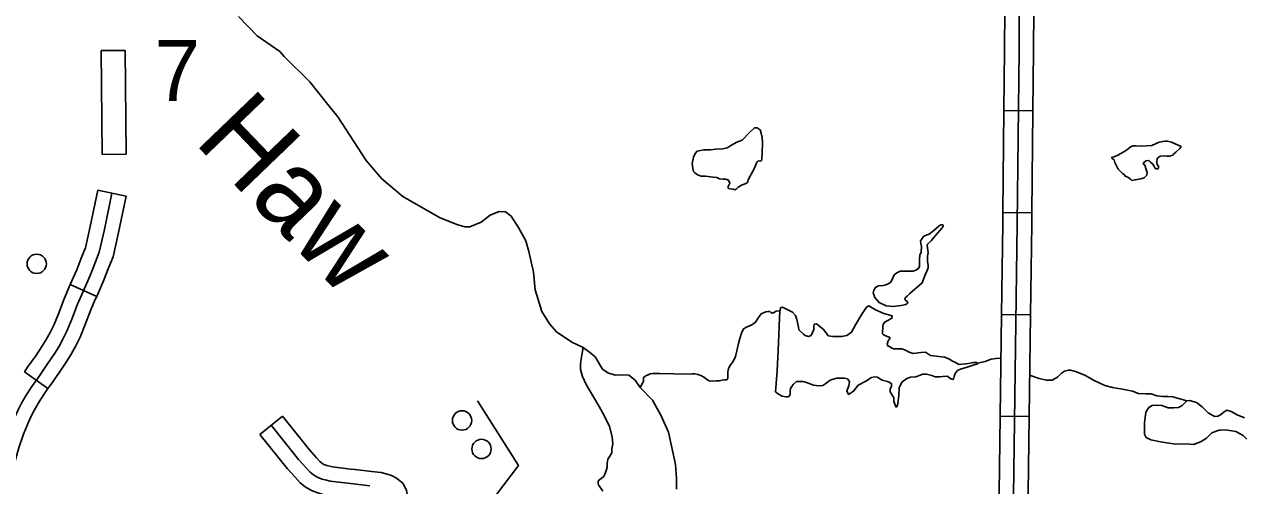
# Model space of a CAD drawing. Extents: x 1382482 to 1385815, y 1168351 to 1170484.
# Drawn here: x 1383658.5 to 1383911.3, y 1169178.5 to 1169274 of the extents above; entities that cross this region are included whole.
import ezdxf

# ---------------------------------------------------------------- set-up
doc = ezdxf.new("R2010")
doc.units = 0
for name, color, linetype in [('32', 7, 'Continuous'), ('35', 7, 'Continuous'), ('45', 7, 'Continuous'), ('57', 7, 'Continuous'), ('Default', 7, 'Continuous')]:
    doc.layers.add(name, color=color, linetype=linetype)

msp = doc.modelspace()

# ---------------------------------------------------------------- linework, layer by layer
at = {"layer": '32'}
for p, q in [((1383867.57, 1169256.11), (1383861.57, 1169256.18)), ((1383673.68, 1169239.69), (1383679.56, 1169238.46)), ((1383867.34, 1169234.99), (1383861.34, 1169235.06)), ((1383667.99, 1169220.11), (1383673.46, 1169217.66)), ((1383867.07, 1169213.87), (1383861.07, 1169213.95)), ((1383658.47, 1169202.04), (1383663.35, 1169198.55)), ((1383866.79, 1169192.75), (1383860.79, 1169192.83))]:
    msp.add_line(p, q, dxfattribs=at)
for points in [[(1383862.28, 1169023.84), (1383862.44, 1169032.46), (1383862.63, 1169053.65), (1383862.71, 1169067.33), (1383862.71, 1169079.26), (1383862.86, 1169103.72), (1383863.17, 1169145.65), (1383864.32, 1169232.68), (1383864.7, 1169268.66), (1383864.78, 1169287.98), (1383865.16, 1169308.27), (1383865.27, 1169315.78)], [(1383861.57, 1169256.18), (1383861.7, 1169268.68), (1383861.74, 1169277.27)], [(1383867.57, 1169256.11), (1383867.7, 1169268.64), (1383867.74, 1169277.25)], [(1383861.34, 1169235.06), (1383861.57, 1169256.18)], [(1383867.34, 1169234.99), (1383867.57, 1169256.11)], [(1383676.62, 1169239.07), (1383675.05, 1169231.55), (1383674, 1169226.81), (1383673.19, 1169224.84), (1383672.13, 1169222.01), (1383670.36, 1169218.07), (1383669.49, 1169216.04), (1383668.3, 1169212.93), (1383667.29, 1169210.46), (1383666.46, 1169208.79), (1383665.58, 1169207.2), (1383664.75, 1169205.89), (1383663.29, 1169203.66), (1383661.58, 1169201.23), (1383659.99, 1169199.01), (1383658.85, 1169197.17), (1383657.87, 1169195.53), (1383657.16, 1169194.19), (1383656.53, 1169192.75), (1383655.47, 1169190.21), (1383654.44, 1169187.16), (1383653.68, 1169184.48), (1383653, 1169182.54), (1383652.14, 1169180.57)], [(1383673.68, 1169239.69), (1383672.12, 1169232.18), (1383671.12, 1169227.71), (1383670.39, 1169225.93), (1383669.35, 1169223.15), (1383667.99, 1169220.11)], [(1383679.56, 1169238.46), (1383677.99, 1169230.92), (1383676.87, 1169225.9), (1383675.98, 1169223.74), (1383674.9, 1169220.87), (1383673.46, 1169217.66)], [(1383861.07, 1169213.95), (1383861.32, 1169232.72), (1383861.34, 1169235.06)], [(1383867.07, 1169213.87), (1383867.32, 1169232.65), (1383867.34, 1169234.99)], [(1383667.99, 1169220.11), (1383667.61, 1169219.28), (1383666.71, 1169217.16), (1383665.51, 1169214.03), (1383664.56, 1169211.7), (1383663.81, 1169210.19), (1383663, 1169208.74), (1383662.22, 1169207.51), (1383660.81, 1169205.34), (1383659.13, 1169202.97), (1383658.47, 1169202.04)], [(1383673.46, 1169217.66), (1383673.11, 1169216.87), (1383672.27, 1169214.91), (1383671.09, 1169211.83), (1383670.03, 1169209.22), (1383669.12, 1169207.39), (1383668.16, 1169205.67), (1383667.27, 1169204.27), (1383665.78, 1169201.97), (1383664.02, 1169199.49), (1383663.35, 1169198.55)], [(1383860.79, 1169192.83), (1383861.07, 1169213.95)], [(1383866.79, 1169192.75), (1383867.07, 1169213.87)], [(1383663.35, 1169198.55), (1383662.49, 1169197.35), (1383661.42, 1169195.61), (1383660.48, 1169194.05), (1383659.86, 1169192.88), (1383659.29, 1169191.57), (1383658.28, 1169189.15), (1383657.3, 1169186.27), (1383656.54, 1169183.58), (1383655.15, 1169179.6)], [(1383860.51, 1169171.71), (1383860.79, 1169192.83)], [(1383866.51, 1169171.63), (1383866.79, 1169192.75)]]:
    msp.add_lwpolyline(points, dxfattribs=at)
at = {"layer": '35'}
for points in [[(1383702.85, 1169275.68), (1383706.7, 1169271.69), (1383711.41, 1169268.41), (1383712.36, 1169267.36), (1383717.64, 1169262.11), (1383721.37, 1169257.46), (1383723.47, 1169254.88), (1383729.33, 1169245.82), (1383732.61, 1169242.01), (1383736.95, 1169238.36), (1383744.57, 1169234), (1383748.15, 1169232.6), (1383749.78, 1169232.07), (1383750.8, 1169232.07), (1383753.2, 1169233.07), (1383755.04, 1169234.51), (1383756.92, 1169235.28), (1383758.21, 1169235.2), (1383759.41, 1169234.28), (1383761.02, 1169231.82), (1383762.42, 1169229.18), (1383763.04, 1169227), (1383764.01, 1169222.68), (1383764.36, 1169219.03), (1383765.76, 1169214.51), (1383767.32, 1169211.99), (1383768.79, 1169210.35), (1383772, 1169208.19), (1383774.33, 1169207.1), (1383775.66, 1169206.09), (1383776.78, 1169205.16), (1383778.34, 1169202.59), (1383779.47, 1169201.82), (1383780.98, 1169201.31), (1383782.5, 1169201.43), (1383783.78, 1169201.31), (1383785.1, 1169200.28), (1383786.17, 1169198.8), (1383788.68, 1169196.14), (1383790.43, 1169193.02), (1383792.05, 1169189.52), (1383793.48, 1169182.82)], [(1383800.72, 1169248.05), (1383801.84, 1169248.21), (1383803.25, 1169248.26), (1383804.17, 1169248.44), (1383805.11, 1169249.04), (1383806.2, 1169249.62), (1383807.3, 1169250.06), (1383808.8, 1169251.64), (1383809.86, 1169252.59), (1383810.41, 1169252.61), (1383811.01, 1169252.17), (1383811.24, 1169251.48), (1383811.45, 1169250.61), (1383811.52, 1169249.55), (1383811.47, 1169247.38), (1383811.4, 1169246.16), (1383811.28, 1169245.82), (1383810.94, 1169245.7), (1383810.64, 1169245.79), (1383810.32, 1169245.52), (1383810.04, 1169244.83), (1383809.81, 1169244.14)], [(1383884.59, 1169245.39), (1383884.43, 1169245.96), (1383884.25, 1169246.14), (1383883.96, 1169246.33), (1383883.93, 1169246.51), (1383884.43, 1169246.58), (1383885.3, 1169246.98), (1383886.63, 1169247.77), (1383887.28, 1169248.2), (1383887.83, 1169248.64), (1383888.37, 1169248.85), (1383888.95, 1169248.85), (1383890.06, 1169248.78), (1383892.2, 1169248.96), (1383893.75, 1169249.65), (1383894.9, 1169249.83), (1383895.48, 1169249.83), (1383896.28, 1169249.61), (1383898.32, 1169248.75)], [(1383809.81, 1169244.14), (1383809.19, 1169243.01), (1383808.98, 1169242.59), (1383808.57, 1169241.81), (1383808.48, 1169241.49), (1383808.38, 1169241.3), (1383808.2, 1169241.17), (1383807.92, 1169241), (1383807.3, 1169240.82), (1383806.82, 1169240.52), (1383806.36, 1169240.22), (1383806.04, 1169239.88), (1383805.76, 1169239.78), (1383805.46, 1169239.9), (1383804.88, 1169239.94), (1383804.45, 1169240.06), (1383804.35, 1169240.29), (1383804.38, 1169240.45), (1383804.63, 1169240.84), (1383804.77, 1169241.17), (1383804.49, 1169241.74), (1383803.94, 1169241.97), (1383803.25, 1169241.99), (1383802.56, 1169242.02), (1383802.01, 1169242.29), (1383801.25, 1169242.41), (1383799.66, 1169242.57), (1383798.81, 1169242.59), (1383798.02, 1169242.87), (1383797.49, 1169243.28), (1383797.22, 1169243.58), (1383797.03, 1169244.27), (1383796.96, 1169245.2), (1383797.19, 1169246.51), (1383797.54, 1169247.27), (1383797.93, 1169247.75), (1383799.33, 1169248.03), (1383800.72, 1169248.05)], [(1383898.32, 1169248.75), (1383898.01, 1169248.35), (1383897.21, 1169247.59), (1383896.78, 1169247.19), (1383896.56, 1169246.94), (1383896.13, 1169246.8), (1383895.81, 1169246.72), (1383895.34, 1169246.76), (1383894.72, 1169246.8), (1383893.98, 1169246.74), (1383893.33, 1169246.27), (1383893.28, 1169245.57), (1383893.28, 1169245.35), (1383893.35, 1169245.03), (1383893.6, 1169244.66), (1383893.6, 1169244.34), (1383893.53, 1169244.19), (1383893.42, 1169244.09), (1383893.35, 1169244.09), (1383893.13, 1169244.12), (1383892.88, 1169244.3), (1383892.63, 1169244.74), (1383892.41, 1169245.1), (1383891.94, 1169245.49), (1383891.62, 1169245.86), (1383891.08, 1169245.79), (1383890.68, 1169245.54), (1383890.46, 1169245.13), (1383890.79, 1169244.84), (1383891.08, 1169243.94), (1383891.29, 1169243.33), (1383891.18, 1169242.79), (1383890.61, 1169242.21), (1383889.96, 1169242.03), (1383888.8, 1169241.81), (1383888.12, 1169241.7), (1383887.79, 1169241.95), (1383887.25, 1169242.35), (1383886.67, 1169242.57), (1383886.56, 1169242.89), (1383886.13, 1169243.15), (1383885.23, 1169244.01), (1383884.59, 1169245.39)], [(1383844.05, 1169223.9), (1383844.08, 1169225.3), (1383844.1, 1169226.22), (1383844.42, 1169226.81), (1383844.49, 1169227.98), (1383844.36, 1169228.62), (1383844.29, 1169229.19), (1383844.47, 1169229.49), (1383844.83, 1169229.99), (1383845.09, 1169230.22), (1383846.05, 1169230.56), (1383847.05, 1169231.36), (1383848.17, 1169232.3), (1383848.53, 1169232.52), (1383848.74, 1169232.5), (1383849.01, 1169232.34), (1383848.83, 1169231.93), (1383847.28, 1169230.19), (1383846.5, 1169229.19), (1383845.73, 1169228.5), (1383845.63, 1169228.23), (1383845.82, 1169227.25), (1383845.89, 1169226.68), (1383845.75, 1169226.04), (1383845.73, 1169224.87), (1383845.89, 1169224.16), (1383845.84, 1169223.57), (1383845.57, 1169222.93), (1383845.26, 1169222.12)], [(1383845.26, 1169222.12), (1383844.6, 1169220.47), (1383843.09, 1169219.19), (1383842.04, 1169218.28), (1383841.49, 1169217.75), (1383841.1, 1169217.39), (1383841.03, 1169217.11), (1383841.26, 1169216.84), (1383841.51, 1169216.64), (1383841.65, 1169216.45), (1383841.6, 1169216.27), (1383841.22, 1169216), (1383840.23, 1169215.79), (1383838.68, 1169215.58), (1383837.13, 1169215.72), (1383835.69, 1169216.43), (1383834.82, 1169217.41), (1383834.61, 1169218.05), (1383834.48, 1169218.44), (1383834.57, 1169218.99), (1383834.91, 1169219.54), (1383835.57, 1169219.83), (1383836.53, 1169219.9), (1383837.06, 1169220.08), (1383837.45, 1169220.2), (1383838.02, 1169220.56), (1383838.38, 1169221.14), (1383838.63, 1169221.66), (1383838.84, 1169222.12), (1383839.39, 1169222.55), (1383840.05, 1169222.87), (1383841.03, 1169222.89), (1383841.51, 1169222.89), (1383842.2, 1169222.92), (1383842.77, 1169222.92), (1383843.32, 1169223.08), (1383843.86, 1169223.47), (1383844.05, 1169223.9)], [(1383815.12, 1169214.66), (1383814.34, 1169214.6), (1383813.86, 1169214.33), (1383813.63, 1169214.19), (1383813.63, 1169214.19), (1383813.22, 1169214.35), (1383813.01, 1169214.51), (1383812.71, 1169214.56), (1383812.19, 1169214.46), (1383811.25, 1169214.03), (1383810.66, 1169213.28), (1383810.09, 1169212.36), (1383809.33, 1169211.81), (1383808.35, 1169211.36), (1383807.58, 1169210.92), (1383807.16, 1169210.06), (1383806.84, 1169208.91), (1383806.52, 1169207.89), (1383806.18, 1169206.38), (1383805.89, 1169205.24), (1383805.42, 1169204.17), (1383804.87, 1169203.49), (1383804.62, 1169203.01), (1383804.41, 1169202.44), (1383804.32, 1169201.87), (1383804.32, 1169201.36), (1383804.32, 1169200.75), (1383804.18, 1169200.47), (1383803.96, 1169200.36), (1383803.66, 1169200.38), (1383803.13, 1169200.34), (1383802.61, 1169200.18), (1383801.9, 1169200.15), (1383801.12, 1169200.13), (1383800.42, 1169200.18), (1383799.98, 1169200.47), (1383799.5, 1169200.86), (1383798.73, 1169201.29), (1383798.09, 1169201.5), (1383797.45, 1169201.61), (1383796.92, 1169201.61), (1383796.35, 1169201.57), (1383793.14, 1169201.64), (1383790.17, 1169201.71), (1383788.67, 1169201.68), (1383788.19, 1169201.61), (1383787.78, 1169201.43), (1383787.32, 1169201.2), (1383787.09, 1169201.04), (1383786.86, 1169200.88), (1383786.84, 1169200.5), (1383786.82, 1169200.04), (1383786.66, 1169199.7), (1383786.17, 1169198.8)], [(1383842.22, 1169200.93), (1383841.45, 1169200.66), (1383840.4, 1169199.88), (1383839.86, 1169198.74), (1383839.76, 1169197.18), (1383839.54, 1169195.4), (1383839.35, 1169194.81), (1383839.17, 1169194.76), (1383838.99, 1169195.17), (1383838.76, 1169195.86), (1383838.71, 1169196.63), (1383838.3, 1169197.32), (1383837.98, 1169197.87), (1383837.98, 1169198.46), (1383838.26, 1169199.06), (1383838.26, 1169199.56), (1383837.94, 1169199.83), (1383837.44, 1169200.06), (1383836.34, 1169200.29), (1383835.65, 1169200.75), (1383835.33, 1169200.93), (1383834.74, 1169201.02), (1383834.1, 1169200.84), (1383832.91, 1169200.11), (1383831.36, 1169199.24), (1383830.4, 1169198), (1383829.35, 1169197.37), (1383828.99, 1169198.1), (1383829.44, 1169199.1), (1383829.58, 1169200.02), (1383829.12, 1169200.56), (1383828.53, 1169200.7), (1383827.84, 1169200.75), (1383826.93, 1169200.7), (1383825.65, 1169200.38), (1383825.06, 1169199.97), (1383824.65, 1169199.6), (1383824.05, 1169199.19), (1383823.41, 1169199.1), (1383822.64, 1169199.19), (1383822.09, 1169199.24), (1383820.63, 1169199.83), (1383819.85, 1169200.02), (1383819.53, 1169200.06), (1383818.57, 1169200.02), (1383817.89, 1169199.38), (1383817.34, 1169198.6), (1383817.25, 1169198.1), (1383817.25, 1169197.27), (1383816.88, 1169196.86), (1383816.38, 1169196.82), (1383815.56, 1169197), (1383814.83, 1169197.41), (1383814.23, 1169197.91), (1383814.55, 1169202.21), (1383814.83, 1169208.01), (1383814.96, 1169211.57), (1383815.12, 1169214.66), (1383815.33, 1169215.37), (1383815.69, 1169215.46), (1383816.24, 1169215.18), (1383817.75, 1169214.41), (1383818.37, 1169213.72), (1383818.6, 1169212.9), (1383818.94, 1169211.3), (1383819.07, 1169210.71), (1383820.03, 1169209.84), (1383820.35, 1169209.56), (1383821.04, 1169209.34), (1383821.59, 1169209.56), (1383821.91, 1169210.16), (1383822.13, 1169210.8), (1383822.13, 1169211.39), (1383822.23, 1169211.89), (1383822.64, 1169211.99), (1383822.91, 1169211.85), (1383823.46, 1169211.39), (1383824.19, 1169210.84), (1383824.83, 1169209.93), (1383825.14, 1169209.52)], [(1383825.14, 1169209.52), (1383826.14, 1169209.33), (1383827.14, 1169209.33), (1383827.97, 1169209.38), (1383829.02, 1169209.56), (1383829.98, 1169210.25), (1383830.8, 1169211.8), (1383832.12, 1169213.99), (1383833.1, 1169215.46), (1383833.55, 1169215.73), (1383834.91, 1169214.86), (1383836.65, 1169214.13), (1383838.38, 1169213.67), (1383838.34, 1169213.13), (1383838.02, 1169212.99), (1383837.65, 1169212.71), (1383836.92, 1169212.39), (1383836.51, 1169211.94), (1383836.46, 1169211.48), (1383836.46, 1169211.07), (1383836.42, 1169210.48), (1383836.37, 1169209.93), (1383836.74, 1169209.61), (1383837.19, 1169209.42), (1383837.7, 1169209.24), (1383837.88, 1169209.2), (1383837.88, 1169208.97), (1383837.56, 1169208.46), (1383837.33, 1169207.78), (1383837.47, 1169207.41), (1383838.67, 1169206.82), (1383839.52, 1169206.82), (1383840.39, 1169206.82), (1383841.17, 1169206.55), (1383841.9, 1169206.13), (1383842.77, 1169205.86), (1383844.32, 1169206.04), (1383845.28, 1169206.09), (1383846.33, 1169205.4), (1383849.25, 1169205.08), (1383850.17, 1169204.72), (1383850.9, 1169204.26), (1383851.08, 1169204.17), (1383852.31, 1169203.53), (1383854.2, 1169203.76), (1383855.25, 1169203.95), (1383855.92, 1169203.99), (1383856.1, 1169203.85), (1383856.06, 1169203.62), (1383855.6, 1169203.53), (1383853.96, 1169203.03), (1383852.59, 1169202.62), (1383851.95, 1169202.3), (1383851.49, 1169201.7), (1383851.22, 1169201.15), (1383851.17, 1169200.7), (1383850.99, 1169200.42), (1383850.39, 1169200.65), (1383849.89, 1169201.11), (1383848.84, 1169201.06), (1383848.38, 1169201), (1383847.33, 1169201.02), (1383846.65, 1169201.25), (1383845.51, 1169201.52), (1383845.23, 1169201.57), (1383845, 1169201.57), (1383844.73, 1169201.57), (1383843.27, 1169200.97), (1383842.22, 1169200.93)], [(1383778.39, 1169177.31), (1383777.53, 1169178.6), (1383777.44, 1169178.88), (1383777.44, 1169179.43), (1383778.08, 1169179.93), (1383778.59, 1169180.35), (1383778.96, 1169181.16), (1383779.28, 1169182.18), (1383779.33, 1169183.1), (1383779.42, 1169183.93), (1383779.88, 1169184.53), (1383780.25, 1169185.22), (1383780.29, 1169186.05), (1383780.48, 1169187.11), (1383780.34, 1169188.58), (1383779.79, 1169190.7), (1383778.73, 1169192.82), (1383777.67, 1169194.83), (1383776.52, 1169196.72), (1383774.95, 1169199.39), (1383774.21, 1169201.05), (1383773.75, 1169202.52), (1383773.8, 1169203.63), (1383773.94, 1169204.73), (1383774.33, 1169207.1)], [(1383860.95, 1169204.85), (1383859.95, 1169204.81), (1383858.9, 1169204.63), (1383857.67, 1169204.17), (1383856.1, 1169203.85)], [(1383899.49, 1169195.99), (1383896.6, 1169196.84), (1383895.56, 1169196.91), (1383894.52, 1169196.95), (1383893.29, 1169197.07), (1383892.1, 1169197.49), (1383890.99, 1169197.49), (1383889.49, 1169197.57), (1383888.22, 1169198.03), (1383886.15, 1169198.45), (1383884.84, 1169198.64), (1383884.07, 1169198.8), (1383882.46, 1169199.18), (1383880.15, 1169200.3), (1383878.35, 1169201.33), (1383876.43, 1169202.1), (1383875.39, 1169202.37), (1383874.97, 1169202.41), (1383874.12, 1169202.14), (1383873.51, 1169201.76), (1383872.7, 1169200.91), (1383871.55, 1169200.34), (1383870.36, 1169200.3), (1383868.88, 1169200.68), (1383866.9, 1169201.33)], [(1383905.75, 1169189.8), (1383904.64, 1169189.42), (1383903.56, 1169188.31), (1383902.45, 1169187.57), (1383900.91, 1169187), (1383900.18, 1169187.04), (1383898.8, 1169187.08), (1383897.14, 1169187.04), (1383894.03, 1169187.5), (1383892.03, 1169187.96), (1383891.07, 1169188.42), (1383890.73, 1169189.11), (1383890.73, 1169191.46), (1383890.96, 1169193.65), (1383891.61, 1169194.65), (1383892.27, 1169195.03), (1383893.15, 1169195.15), (1383894.3, 1169195.03), (1383895.65, 1169194.57), (1383896.76, 1169194.57), (1383897.76, 1169194.65), (1383898.49, 1169195.07), (1383899.22, 1169195.76), (1383899.49, 1169195.99), (1383900.1, 1169196.07), (1383900.76, 1169195.88), (1383901.49, 1169195.68), (1383902.68, 1169194.76), (1383903.91, 1169193.57), (1383904.75, 1169193.03), (1383905.29, 1169192.76)], [(1383905.29, 1169192.76), (1383905.94, 1169192.84), (1383906.44, 1169193.11), (1383907.21, 1169193.72), (1383907.79, 1169194.07), (1383908.71, 1169193.84), (1383909.29, 1169193.46), (1383909.9, 1169193.15), (1383911.44, 1169192.53)], [(1383911.9, 1169188.07), (1383911.17, 1169188.84), (1383909.63, 1169189.69), (1383907.52, 1169190), (1383906.44, 1169189.92), (1383906.17, 1169189.92), (1383905.75, 1169189.8)], [(1383793.48, 1169182.82), (1383793.66, 1169179.92), (1383793.71, 1169177.75)]]:
    msp.add_lwpolyline(points, dxfattribs=at)
at = {"layer": '45'}
msp.add_line((1383707.32, 1169189.07), (1383712.01, 1169192.82), dxfattribs=at)
for points in [[(1383709.66, 1169190.95), (1383715.3, 1169183.9), (1383716.82, 1169182.2), (1383717.7, 1169181.25), (1383718.41, 1169180.68), (1383719.29, 1169180.15), (1383720.23, 1169179.8), (1383721.08, 1169179.55), (1383721.88, 1169179.38), (1383726.69, 1169178.8), (1383730.12, 1169178.41)], [(1383712.01, 1169192.82), (1383717.6, 1169185.84), (1383719.04, 1169184.22), (1383719.75, 1169183.45), (1383720.14, 1169183.14), (1383720.59, 1169182.86), (1383721.18, 1169182.65), (1383721.83, 1169182.46), (1383722.38, 1169182.34), (1383726.08, 1169181.89)], [(1383707.32, 1169189.07), (1383713.01, 1169181.96), (1383714.6, 1169180.18), (1383715.65, 1169179.05), (1383716.69, 1169178.22), (1383717.98, 1169177.43), (1383719.29, 1169176.95), (1383720.34, 1169176.64), (1383721.38, 1169176.41), (1383725.37, 1169175.94)], [(1383726.08, 1169181.89), (1383727.04, 1169181.78), (1383730.47, 1169181.39), (1383732.41, 1169181.16), (1383733.7, 1169180.86), (1383734.61, 1169180.56), (1383735.63, 1169180.03), (1383737.01, 1169178.89), (1383737.72, 1169177.47), (1383738, 1169175.93), (1383738.04, 1169174.02), (1383738.18, 1169172.7), (1383738.26, 1169171.98), (1383738.48, 1169170.93), (1383738.89, 1169168.99), (1383739.12, 1169167.37), (1383739.27, 1169165.97), (1383739.29, 1169165.37)]]:
    msp.add_lwpolyline(points, dxfattribs=at)
at = {"layer": '57'}
for p, q in [((1383679.38, 1169268.65), (1383674.38, 1169268.61)), ((1383674.38, 1169268.61), (1383674.58, 1169247.11)), ((1383679.58, 1169247.16), (1383679.38, 1169268.65)), ((1383674.58, 1169247.11), (1383679.58, 1169247.16))]:
    msp.add_line(p, q, dxfattribs=at)
at = {"layer": 'Default'}
msp.add_lwpolyline([(1383752.42, 1169195.99), (1383760.91, 1169182.59), (1383747.93, 1169165.46)], dxfattribs=at)
for centre in [(1383661.02, 1169224.42), (1383749.21, 1169191.96), (1383753.25, 1169186.05)]:
    msp.add_circle(centre, 2, dxfattribs=at)

# ---------------------------------------------------------------- texts
at = {"layer": '35'}
msp.add_text('Haw', height=16.896, rotation=313.8622, dxfattribs=at).set_placement((1383693.41, 1169249.71))
at = {"layer": '57'}
msp.add_text('7', height=12.67, dxfattribs=at).set_placement((1383685.45, 1169258.16))

doc.saveas('drawing.dxf')
